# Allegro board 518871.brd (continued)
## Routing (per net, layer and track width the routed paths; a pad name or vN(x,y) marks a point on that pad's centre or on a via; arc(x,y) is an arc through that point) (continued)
GND_EARTH: length 19.9
  TOP w0.508: 7.77,114.68 2.26,114.68 J7.8 J7.6
VBAT: length 6.3
  TOP w0.508: 125.35,29.03 J4.1 ; J4.1 126.92,30.61 ; J4.1 125.35,32.18 ; J4.1 123.77,30.61
VBAT_SYS: length 43.3
  TOP w0.203: U18.15 v1(33.15,18.67)
  TOP w0.305: U79.10 v1(105.41,62.36)
  TOP w0.508: U606.5 118.13,105.01 v1(118.49,104.65) 118.93,105.08 U606.6
  TOP w0.635: TP1.1 99.95,27.23 ; TP1.1 99.26,26.54 ; TP1.1 100.64,26.54 ; TP1.1 99.95,25.86 ; 93.93,19.05 C23.1 ; C23.1 95.25,20.37 ; C23.1 95.25,17.73 ; C23.1 96.57,19.05 ; 53.92,19.05 C3.1 ; C3.1 56.57,19.05 ; C3.1 55.24,17.73
  LY5_PWR w0.635: C1.1 95.25,37.52 ; C1.1 93.93,36.2 ; C1.1 96.57,36.2 ; C1.1 95.25,34.87 ; 53.92,19.05 C3.1 ; C3.1 55.24,20.37 ; C3.1 56.57,19.05 ; C3.1 55.24,17.73 ; C23.1 96.57,19.05 ; C23.1 93.93,19.05 ; C23.1 95.25,20.37 ; C23.1 95.25,17.73 ; 55.24,34.87 C2.1 ; C2.1 55.24,37.52 ; C2.1 56.57,36.2 ; C2.1 53.92,36.2 ; TP1.1 100.64,26.54 ; TP1.1 99.95,25.86 ; TP1.1 99.26,26.54 ; TP1.1 99.95,27.23
  BOTTOM w0.305: RJ27.1 v1(105.41,62.36) C566.1
  vias: v1(16.89,15.11) v1(16.89,14.1) v1(18.16,15.11) v1(18.16,14.1) v1(19.43,15.11) v1(19.43,14.1) v1(24.64,19.05) v1(24.64,18.16) v1(25.4,19.05) v1(25.4,18.16) v1(26.16,19.05) v1(26.16,18.16) v1(33.02,17.65) v1(33.02,16.51) v1(37.08,16.26) v1(86.23,118.75) v1(86.23,117.47) v1(86.23,116.46) v1(90.17,117.86) v1(91.31,117.86) v1(92.46,117.86) v1(94.49,117.86) v1(95.63,117.86) v1(96.77,117.86) v1(100.08,24.26) v1(100.08,23.37) v1(100.08,22.48) v1(100.08,21.59) v1(102.49,26.04) v1(103.89,24.64) v1(103.89,23.24) v1(103.89,21.72)
VCC_LED_30V: length 18.9
  TOP w0.508: C628.1 v1(108.08,116.97) ; v1(110.36,116.97) 110.49,116.84 C635.2 111.38,114.3 112.14,113.54 112.14,112.52 112.56,112.11 U606.26
  LY4 w0.635: J24.3 125.81,77.19 ; J24.3 124.46,78.54 ; J24.3 123.11,77.19 ; J24.2 124.46,81.53 ; J24.2 124.46,78.84 ; J24.2 125.81,80.19 ; J24.2 123.11,80.19
  vias: v1(99.95,116.97) v1(101.09,116.97) v1(102.23,116.97) v1(103.38,116.97) v1(105.79,116.97) v1(106.93,116.97) v1(109.22,116.97)
VCC_LM5141: length 7.7
  TOP w0.305: U18.10 29.59,21.34 28.65,22.28 C45.1 26.47,22.28 25.48,21.29 D5.2
VDD__TX: length 1.8
  TOP w0.305: v1(86.82,88.34) 86.89,88.27 C429.1
  BOTTOM w0.305: v1(86.82,88.34) U77.31
VDD_CORE_AVS: length 114
  TOP w0.102: 49.33,85.62 49.72,85.62 ; 47.14,79.11 46.72,79.11 46.71,79.1 ; v3(47.9,85.62) 47.84,85.62 48.44,85.62 ; 50.63,85.62 51.02,85.62 ; 47.12,85.62 46.73,85.62
  TOP w0.203: U27.V10 52.13,84.64 U27.U9 ; U27.N11 U27.P10 ; U27.M17 U27.N18 ; 49.72,85.62 v3(49.85,85.62) ; U27.J16 47.25,79.11 47.14,79.11 ; U27.V12 50.51,85.62 50.63,85.62 ; 48.44,85.62 48.55,85.62 U27.V14 ; U27.N15 U27.P14 ; U27.J18 46.71,79.1 ; 47.12,85.62 47.25,85.62 U27.V16 ; U27.V18 46.61,85.62 46.73,85.62 ; U27.L12 U27.M11 ; v3(49.2,85.62) 49.33,85.62 ; v3(51.15,85.62) 51.02,85.62 51.02,85.62 ; 50.18,83.34 U27.R12 ; 48.02,85.62 v3(47.9,85.62) ; U27.K18 U27.L17 ; U27.N13 U27.P12 ; U27.R10 U27.T9
  TOP w0.254: U27.W12 v3(49.85,85.62) U27.V12 ; U27.T15 48.23,83.99 U27.R16 v3(47.25,83.67) ; U27.T15 v3(48.55,84.32) U27.U15 ; U27.T15 U27.R14 U27.T13 ; U27.T13 U27.R12 U27.T11 ; U27.T13 v3(49.85,84.32) U27.U13 ; U27.K18 v3(45.95,79.77) U27.J18 ; U27.V16 v3(47.9,85.62) U27.W16 ; U27.T11 v3(51.15,84.32) U27.U11 ; U27.T11 50.83,83.99 U27.R10 ; v3(50.5,83.02) 50.5,83.02 50.18,83.34 ; U27.V18 v3(46.6,84.97) 46.53,84.92 U27.U18 ; U27.P18 U27.R17 U27.P16 ; U27.W10 v3(51.15,85.62) U27.V10 ; U27.T9 v3(52.45,84.32) U27.U9 ; U27.V14 v3(49.2,85.62) U27.W14
  TOP w0.305: U27.P14 v3(49.2,83.02) U27.R14 ; U27.J16 47.9,79.68 U27.J15 ; U27.N15 v3(48.55,81.72) U27.M15 ; v3(47.9,83.02) U27.R16 ; U27.N13 v3(49.85,81.72) U27.M13 ; U27.M17 v3(47.25,81.07) U27.L17 ; v3(50.5,80.42) U27.K12 ; U27.N11 v3(51.15,81.72) U27.M11 ; v1(41.27,48.01) 41.66,48.39 U602.8 ; U27.P12 v3(50.5,83.02) ; U27.R10 v3(51.8,83.02) U27.P10 ; U27.P18 v3(45.95,82.37) U27.N18 ; U27.R17 v3(47.25,83.67) U27.T17
  LY5_PWR w0.102: v1(41.27,48.01) 41.34,48.01 43.56,50.23 43.56,50.85 44.81,52.1 44.81,52.6 44.07,53.34 44.07,60.07 48.39,64.39 50.8,64.39 50.95,64.24 51.66,64.24 52.45,65.02 59.82,65.02 61.34,66.55 61.34,67.44 61.21,67.56 61.21,70.38 61.57,70.74 61.57,73.56 58.04,77.09 58.04,78.74 56.64,80.14 52.7,80.14 52.58,80.26
  BOTTOM w0.254: v3(50.5,80.42) 50.68,80.65 50.9,80.87 50.93,80.87 C347.1 ; C321.1 v3(49.85,85.62) ; C332.1 v3(50.5,83.02) ; C341.1 v3(48.55,81.72)
  BOTTOM w0.381: C348.1 49.85,81.71 v3(49.85,81.72) ; v1(63.63,82.62) 63.63,82.42 64.01,82.03 C344.1 ; v1(63.16,87.58) C303.1 v1(65.71,87.58) ; v2(65.66,80.03) C373.1 v2(63.19,80.03) ; C347.1 51.16,81.72 v3(51.15,81.72)
  BOTTOM w0.406: C344.1 64.75,82.03 65.15,82.44 v1(65.15,82.62) ; v1(60.02,90.37) C551.1 v1(62.41,90.37) ; v1(62.61,83.93) C323.1 65.22,83.93 v1(65.28,83.99)
  vias: v1(46.86,50.8) v1(47.62,52.32) v1(48.51,52.32) v1(49.53,53.47) v1(49.53,52.58) v1(49.53,51.69) v1(49.53,50.8)
VDD_DDR_1V35: length 126.1
  TOP w0.254: U27.W20 v3(44.65,85.62) U27.V20 ; U27.T20 v3(45.3,84.32) U27.T19 ; v1(5.02,77.08) C98.1 v1(7.43,77.08) ; v1(7.24,84.33) C89.1 v1(4.83,84.33) ; U27.W17 v3(46.6,86.27) 46.28,85.95 U27.W18
  TOP w0.305: U29.R9 v2(9.51,74.51) ; U29.K8 v2(13.51,75.31) ; C80.2 12.13,100.52 v1(10.79,99.19) ; U29.K2 v2(13.51,80.9) ; U29.E9 v2(18.31,74.51) ; U23.R1 v2(9.51,95.93) ; U23.A8 v2(21.51,89.53) ; U23.K8 v2(13.51,89.53) ; v1(24.84,78) C96.1 v1(23.55,78.03) ; U29.H9 v2(15.91,74.51) ; U23.N1 v2(11.11,95.93) ; U29.A1 v2(21.51,81.7) ; U23.C1 v2(19.91,95.93) ; U29.N1 v2(11.11,81.7) ; U29.B2 v2(20.71,80.9) ; U29.N9 v2(11.11,74.51) ; U23.C9 v2(19.91,88.73) ; U29.G7 v2(16.71,76.11) ; U23.E9 v2(18.31,88.73) ; U23.D9 v2(19.11,88.73) ; U29.D2 v2(19.11,80.9) ; v1(5.51,91.74) C84.1 v1(6.93,91.74) ; U23.H2 v2(15.91,95.13) ; U23.N9 v2(11.11,88.73) ; U23.R9 v2(9.51,88.73) ; U29.H2 v2(15.91,80.9) ; v1(32.38,59.69) 36.58,59.69 37.59,58.68 U602.21 ; U29.F1 v2(17.51,81.7) ; U23.B2 v2(20.71,95.13) ; U29.R1 v2(9.51,81.7) ; U23.H9 v2(15.91,88.73) ; U29.D9 v2(19.11,74.51) ; U23.F1 v2(17.51,95.93) ; U29.C9 v2(19.91,74.51) ; U23.G7 v2(16.71,90.33) ; U29.C1 v2(19.91,81.7) ; U23.K2 v2(13.51,95.13) ; U23.A1 v2(21.51,95.93) ; U23.D2 v2(19.11,95.13) ; U29.A8 v2(21.51,75.31)
  LY5_PWR w0.102: 45.34,83.31 45.34,81.15 44.31,80.12 39.1,80.12 32.13,73.15 32.13,68.67 32.17,68.63 32.17,59.91 v1(32.38,59.69)
  BOTTOM w0.254: C300.1 v2(21.51,89.53) ; C279.1 v2(17.51,95.93) ; v2(39.45,91.24) 39.81,91.6 C293.1 39.81,91.9 v2(40.25,92.35) ; C278.1 v2(21.51,95.93) ; C383.1 v2(15.91,74.51) ; v3(44.65,85.62) 44.52,85.75 C315.1 ; v2(36.35,90.2) 36.58,90.2 C295.1 37.05,90.52 v2(37.47,90.94) ; C319.1 v3(46.6,86.27) ; C337.1 v2(17.51,81.7) ; v2(37.97,90.5) 38.31,90.85 C294.1 38.43,91.06 v2(38.84,91.47) ; v2(34.49,87.36) C311.1 v2(34.49,86) ; v2(32.72,85.98) C312.1 v2(32.72,87.33) ; v2(39.88,90.68) 40.01,90.56 C297.1 v2(40.77,90.04) ; 30,87.5 29.7,87.8 C307.1 ; C280.1 v2(11.11,95.93) ; C336.1 v2(21.51,81.7) ; C305.1 v2(15.91,88.73) ; C304.1 v2(19.91,88.73) ; C382.1 v2(19.91,74.51) ; C378.1 v2(21.51,75.31) ; C338.1 v2(11.11,81.7)
  BOTTOM w0.305: v1(17.42,99.19) C273.1 v1(17.37,97.38) ; v1(20.65,97.38) C272.1 v1(20.62,99.19) ; v1(23.05,75.69) C377.1 ; v1(15.82,85.65) C314.1 v1(15.8,87.07) ; v1(10.79,84.96) C328.1 v1(10.79,83.19) ; v1(17.65,84.96) C327.1 v1(17.14,83.19) ; v1(8.64,71.88) C386.2 v1(8.64,73.79) ; v1(10.79,99.19) C274.1 v1(10.79,97.41) ; v1(19.84,72.85) C391.1 v1(19.79,71.42) ; v1(15.62,71.47) C392.1 v1(15.56,73.03) ; C325.1 45.33,84.29 v3(45.3,84.32) ; v1(20.7,84.91) C326.1 v1(20.62,83.24) ; v1(19.84,85.65) C313.1 v1(19.81,87.07) ; C299.1 v1(23.05,89.92)
  BOTTOM w0.381: v2(26.75,80.14) C352.1 v2(26.75,81.46) ; v2(28.52,81.45) C351.1 v2(28.52,80.14) ; v2(30.38,81.42) C354.1 v2(30.38,80.12) ; v2(29.59,88.78) 29.46,88.65 29.46,87.95 C307.1 ; v2(30.63,87.5) 30,87.5
  BOTTOM w0.406: v2(39.25,94.12) C289.1 v2(41.71,94.12)
  vias: v1(4.7,63.5) v1(6.99,63.5) v1(8,63.5) v1(9.78,63.5) v1(12.32,56.52) v1(12.32,55.5) v1(12.32,54.48) v1(12.32,53.47) v1(12.45,58.04) v1(12.57,49.4) v1(12.7,63.63) v1(13.34,58.04) v1(14.1,63.63) v1(14.22,58.04) v1(15.37,63.63) v1(17.78,63.63) v1(19.18,63.63) v1(20.7,63.63) v1(29.72,53.21) v1(32.26,54.74) v1(32.26,53.09) v1(32.38,53.98)
VDD_DSP_AVS: length 77.8
  TOP w0.102: 52.45,78.47 v3(52.45,77.82) ; v3(50.5,77.82) 50.5,78.47 50.51,78.47 ; 49.97,78.48 49.97,78.47 50.39,78.47 ; 49.98,79.77 50.38,79.77 ; 51.68,78.47 51.28,78.47
  TOP w0.203: 51.28,78.47 51.15,78.47 ; 51.81,78.47 51.68,78.47 ; 50.38,79.77 50.5,79.77 ; 49.84,79.75 49.85,79.77 49.98,79.77 ; 50.51,78.47 50.39,78.47 ; 49.97,78.48 49.85,78.48
  TOP w0.305: U27.J9 v3(52.45,79.12) U27.H9 ; U602.1 v1(37.59,49.66) ; U27.H11 50.83,78.79 v3(51.15,79.12) U27.J11 50.5,79.77 ; U27.H11 50.51,78.47 ; U27.H11 51.15,78.47 ; U27.J13 49.53,79.44 v3(49.2,79.12) U27.H13 ; U27.J13 v3(49.85,79.12) 49.85,79.12 U27.H13 ; U27.J13 49.53,79.44 49.84,79.75 ; U27.H13 49.85,78.48 ; U27.H9 52.45,78.47 ; U27.H9 51.81,78.47
  LY5_PWR w0.102: 57.02,78.61 57.4,78.61 57.53,78.49 57.53,76.96 60.96,73.53 60.96,70.87 60.83,70.74 60.83,69.72 60.33,69.21 60.33,66.29 59.44,65.41 51.18,65.41 50.67,64.9 46.71,64.9 43.56,61.75 43.56,53.21 43.15,52.81 43.15,52.16 43.18,52.13 43.18,50.42 41.38,48.62 38.63,48.62 v1(37.59,49.66)
  BOTTOM w0.254: C362.1 v3(51.15,79.12) ; v2(59.8,70.93) C393.1 58.06,72.66 v2(58.05,72.66) ; v3(49.85,79.12) C361.1 ; v2(54.25,70.99) 54.27,70.98 C403.1 v2(54.27,68.46)
  BOTTOM w0.305: C357.1 52.92,79.57 52.65,79.31 v3(52.45,79.12) ; C370.1 v3(52.45,77.82)
  BOTTOM w0.381: v2(38.45,72.29) 38.45,72.29 39.4,73.22 40.28,74.08 v2(40.31,74.08)
  BOTTOM w0.406: v2(52.13,71) C402.1 v2(52.13,68.55) ; v2(48.59,71) C401.1 v2(48.59,68.56)
  vias: v1(29.72,51.44) v1(32.26,50.04) v1(32.38,51.69) v1(32.38,50.8) v1(33.64,66.77) v1(34.23,66.09) v1(34.84,66.72) v1(35.32,66.11) v1(35.98,66.77) v1(36.51,66.11) v1(37.2,66.72) v1(37.68,66.11) v1(38.24,66.75) v1(38.87,66.11) v1(39.46,66.72)
VDD_VID: length 14.3
  TOP w0.305: v1(86.87,87) C568.1 ; L16.1 v1(98.17,80.14) ; v1(87.5,80.64) 87.63,80.77 C410.1 ; C129.1 v1(98.17,78.61) ; C409.1 v1(96.52,80.61)
  TOP w0.508: v1(86.87,87) 85.85,85.98 85.85,81.79 87,80.64 v1(87.5,80.64)
  BOTTOM w0.305: v1(96.52,80.61) U77.64 ; U77.28 87.02,86.84 v1(86.87,87) ; 88.33,80.64 v1(87.5,80.64)
VDDA_LM5141: length 12.1
  TOP w0.203: v1(30.86,27.3) R35.2 R34.2 ; U18.2 34.15,24.37 34.42,24.64 v1(34.42,24.7) C53.1
  BOTTOM w0.305: v1(30.86,27.3) 31.5,27.94 33.27,27.94 34.04,27.18 34.04,25.08 v1(34.42,24.7) 34.99,25.27 R221.2
VDDI_MMC2: length 2.7
  TOP w0.305: U31.E4 v1(78.77,67.75)
  BOTTOM w0.305: C433.1 79.38,68.35 v1(78.77,67.75) 78.7,67.82 C436.1
VDDR_VREFSTL: length 129.5
  TOP w0.254: C164.2 v2(10.16,45.47) ; U29.M8 v2(11.91,75.31) ; U27.Y20 v3(44.65,86.92) ; C91.1 v1(16.05,84.33)
  TOP w0.305: U35.6 10.21,45.52 v2(10.16,45.47) ; U23.H1 v2(15.91,95.93) ; U23.M8 v2(11.91,89.53) ; C91.1 15.3,85.14 14.8,85.64 v1(12.58,85.64) ; U29.H1 v2(15.91,81.7)
  TOP w0.381: v2(15.91,95.93) 15.91,98.01 C82.1 C80.1
  TOP w0.508: v1(3.68,62.48) 3.68,69.98 4.83,71.12 9.4,71.12 v1(10.16,71.88) 10.79,71.25 13.59,71.25 14.35,72.01 v2(14.35,74.3)
  LY3 w0.381: v2(11.91,89.53) 11.98,89.53 12.58,88.93 12.58,85.64 v1(12.58,85.64)
  LY4 w0.381: v2(15.91,95.93) 16.43,96.45 22.17,96.45 22.71,95.91 35.53,95.91 37.08,94.36 37.21,94.36 40.64,90.93 40.64,90.65 40.25,90.26 40.25,87.89 41.53,86.61 43.18,86.61 43.43,86.36 44.32,86.36 44.65,86.69 v3(44.65,86.92)
  BOTTOM w0.305: C386.1 v1(10.16,71.88)
  BOTTOM w0.381: v2(11.91,75.31) 11.94,75.31 13.29,73.96 14.02,73.96 v2(14.35,74.3) 15.22,75.17 15.22,81.02 v2(15.91,81.7) 15.91,82.84 16.1,83.03 16.1,84.28 v1(16.05,84.33) 15.1,85.28 15.1,88.38 15.39,88.67 15.39,90.54 15.7,90.85 18.95,90.85 19.33,91.23 19.33,93.4 18.92,93.81 15.7,93.81 15.39,94.11 15.39,95.34 15.72,95.67 15.72,95.74 v2(15.91,95.93)
  BOTTOM w0.508: v2(10.16,45.47) 10.16,46.99 8.64,48.51 8.64,57.53 v1(3.68,62.48)
VDDS_1V8: length 87.9
  TOP w0.254: U27.W7 v3(53.1,85.62) ; U27.Y18 v3(45.95,86.27) U27.Y19 v3(45.95,86.92) ; v3(45.95,87.57) U27.AA19 ; v3(44.65,83.02) U27.P20 ; U27.G11 50.83,78.14 v3(51.15,77.82) ; U27.H20 v3(44.65,78.47) ; U27.P7 v3(53.1,83.02) U27.R7 ; v3(53.75,79.77) U27.J7 ; U27.H7 53.58,78.65 53.58,78.29 U27.G7 v3(53.75,77.82) U27.F7
  TOP w0.305: U31.P3 v1(77.77,57.74) ; L17.2 v1(87.88,93.73) ; U31.H8 v1(83.77,64.75) ; U31.P8 v1(83.77,57.74) ; U31.L7 v1(82.77,60.74) ; U26.2 52.68,121.92 51.43,121.92 v1(51.31,122.05) ; U27.K8 v3(52.46,79.77) 52.78,79.44 U27.J8 ; U31.L4 v1(78.77,60.74) ; L16.2 v1(101.47,80.14) ; U31.L9 v1(84.78,60.74) ; U31.L2 v1(76.77,60.74) ; U31.H3 v1(77.77,64.75)
  TOP w0.381: v2(36.09,75.41) C108.1 38.2,75.41 v2(38.35,75.56)
  LY4 w0.203: v3(51.15,77.82) 50.75,78.22 49.16,78.22 48.9,78.49 48.5,78.49
  LY4 w0.508: v1(71.27,114.55) 68.58,114.55 65.79,117.35 61.09,117.35 54.48,123.95 53.21,123.95 v1(51.31,122.05)
  BOTTOM w0.254: C318.1 v3(53.1,85.62) ; C298.1 45.95,89.15 v3(45.95,87.57) v3(45.95,86.92) 45.96,86.84 v3(45.95,86.27)
  BOTTOM w0.305: RJ22.3 v1(91.95,76.33) ; v1(95.24,74.81) 95.5,75.07 RJ21.3 ; RJ25.3 RJ23.3 RJ18.3 ; RJ25.3 v1(81.15,83.82) ; RJ25.3 RJ24.3 RJ30.1 ; R271.1 75.95,59.92 v1(76.77,60.74) ; RJ28.1 v1(84.84,87.76) ; RJ29.1 v1(101.47,87.12) ; R296.2 79.49,61.47 v1(78.77,60.74) ; RJ17.1 v1(101.47,84.2) ; v1(72.01,114.3) 71.77,114.06 P9.40 ; v3(53.1,83.02) 53.16,83.07 C342.1 ; R269.1 v1(77.72,62.74) R273.1 ; R300.1 82.25,55.88 82.55,56.18 v1(82.55,56.52) ; P9.38 v1(71.27,114.55) ; v1(82.77,60.74) 82.93,60.59 R289.1 ; C283.1 53.79,79.73 v3(53.75,79.77) ; v1(51.31,122.05) 51.44,122.17 R245.1 R246.1 ; v1(83.77,57.74) 83.57,57.53 C427.1 ; R295.1 v1(81.79,58.8) ; RJ20.3 v1(97.66,77.6) ; R241.2 v1(74.68,81.28) ; v1(83.77,64.75) 83.57,64.54 C411.1 ; R254.1 v1(79.76,88.9) ; v1(84.78,60.74) 84.81,60.71 R268.1 R270.1 ; R250.1 v1(78.49,88.9) ; RJ16.1 v1(100.71,81.28) ; R247.2 v1(77.22,81.28) ; R243.2 v1(75.95,81.28) ; v1(81.79,62.74) 81.92,62.61 R272.1 ; R258.1 v1(81.03,88.9) ; RJ19.3 v1(94.11,77.6)
  vias: v1(67.69,95) v1(68.58,95) v1(68.58,94.11) v1(68.58,93.22)
CAN_POWER_ON_HV: length 94.4
  TOP w0.127: SW2.4 27.81,37.08 v1(33.66,42.93)
  LY4 w0.133: v1(33.66,42.93) 95.89,42.93 109.22,56.26 v1(109.22,57.02)
  BOTTOM w0.127: R436.1 v1(109.22,57.02)
CAN_WAKE: length 17.8
  BOTTOM w0.127: J17.10 115.52,59.89 114.05,58.42 110.62,58.42 v1(106.68,62.36) ; RJ27.2 105.16,61.34 106.17,62.36 v1(106.68,62.36) ; v1(106.68,62.36) R435.2
CANH_1: length 20.2
  TOP w0.127: U79.13 101.6,65.15 103.12,66.67 109.73,66.67 112.5,63.91 J17.4
  BOTTOM w0.127: J17.4 116.2,64.01 R388.1
CANL_1: length 19.3
  TOP w0.127: J17.3 116.23,61.98 113.28,61.98 109.22,66.04 103.76,66.04 102.87,65.15 U79.12
  BOTTOM w0.127: R152.2 116.13,61.72 J17.3
CON_MMC1_CLK: length 8.3
  BOTTOM w0.127: R406.2 109.47,92.33 110.36,92.33 110.46,92.43 111.73,92.43 112.15,92.84 U67.3 112.58,92.84 114.81,92.84 115.28,92.36 P10.5
CON_MMC1_CMD: length 8
  BOTTOM w0.127: P10.3 112.09,94.56 111.37,93.85 U67.5 109.1,93.85 R405.2
CON_MMC1_DAT0: length 8.6
  BOTTOM w0.127: R407.2 109.1,91.31 U66.5 111.33,91.31 111.84,91.82 113.41,91.82 115.07,90.16 P10.7
CON_MMC1_DAT1: length 8.5
  BOTTOM w0.127: R408.2 109.6,90.04 109.82,89.83 111.8,89.83 112.28,90.3 U66.3 114.17,90.3 115.4,89.07 P10.8
CON_MMC1_DAT2: length 8
  BOTTOM w0.127: R403.2 109.1,96.39 U68.5 111.37,96.39 111.89,96.9 114.05,96.9 114.18,96.76 P10.1
CON_MMC1_DAT3: length 8.2
  BOTTOM w0.127: R404.2 109.47,94.87 110.74,94.87 110.84,94.97 111.86,94.97 112.28,95.38 U68.3 113.55,95.38 113.83,95.66 P10.2
CONN_USB_D+: length 9.7
  TOP w0.13: v2(9.53,119.05) 9.32,119.25 8,119.25 J7.3
  BOTTOM w0.122: v2(9.53,119.05) 9.83,119.35 16.6,119.35 16.71,119.24 U52.14
CONN_USB_D-: length 9.7
  TOP w0.13: J7.2 8.04,119.76 9.37,119.76 v2(9.53,119.91)
  BOTTOM w0.122: v2(9.53,119.91) 9.8,119.63 16.61,119.63 16.71,119.74 U52.15
EMAC[1]_RXC: length 72.3
  TOP w0.127: U40.27 v1(92.23,55.6) ; U27.E11 v3(50.5,76.52)
  LY3 w0.133: v1(92.23,55.6) 91.82,56.01 91.59,56.01 91.43,55.85 91.43,55.66 91.27,55.5 91.05,55.5 90.9,55.66 90.9,56.23 90.74,56.39 90.52,56.39 90.36,56.23 90.36,55.66 90.21,55.5 89.99,55.5 89.83,55.66 89.83,56.22 89.66,56.39 89.03,56.39 87.25,54.61 67.69,54.61 67.18,54.1 64.23,54.1 64.08,54.26 64.08,54.45 63.92,54.61 63.7,54.61 63.55,54.45 63.55,54.26 63.39,54.1 63.17,54.1 63.01,54.26 63.01,54.45 62.86,54.61 62.63,54.61 62.48,54.45 62.48,54.26 62.32,54.1 62.1,54.1 61.95,54.26 61.95,54.45 61.79,54.61 61.57,54.61 61.41,54.45 61.41,54.26 61.26,54.1 61.03,54.1 60.88,54.26 60.88,54.45 60.72,54.61 60.5,54.61 60.34,54.45 60.34,54.26 60.19,54.1 59.97,54.1 59.81,54.26 59.81,54.45 59.66,54.61 59.43,54.61 59.28,54.45 59.28,54.26 59.12,54.1 58.9,54.1 58.74,54.26 58.74,54.45 58.59,54.61 58.37,54.61 58.21,54.45 58.21,54.26 58.06,54.1 57.83,54.1 57.68,54.26 57.68,54.45 57.52,54.61 57.3,54.61 57.14,54.45 57.14,54.26 56.99,54.1 56.77,54.1 56.61,54.26 56.61,54.45 56.45,54.61 55.89,54.61 v1(55.5,54.23)
  BOTTOM w0.127: v3(50.5,76.52) 51.12,75.9 51.12,73.98 50.67,73.53 50.67,64.39 51.31,63.75 53.34,63.75 54.23,62.87 54.23,62.23 54.74,61.72 54.74,58.04 55.5,57.28 v1(55.5,54.23)
EMAC[1]_RXCTL: length 73.9
  TOP w0.127: U27.F11 v3(50.5,77.17) ; U40.15 v1(98.54,53.2)
  LY3 w0.133: v1(53.47,54.23) 54.48,54.23 54.99,53.72 67.44,53.72 67.99,54.27 87.67,54.27 88.53,55.13 91.69,55.13 91.95,54.86 96.88,54.86 v1(98.54,53.2)
  BOTTOM w0.102: v3(50.5,77.17) 49.99,77.17 49.02,76.2 49.02,74.33 49.19,74.17 49.19,73.65 49.15,73.61 49.15,73.51
  BOTTOM w0.127: v1(53.47,54.23) 53,54.23 51.18,56.05 51.18,58.42 49.15,60.45 49.15,73.51
EMAC[1]_RXD0: length 71.7
  TOP w0.127: U27.D13 v3(49.85,75.87) ; U40.26 v1(93.37,56.36)
  LY3 w0.133: v1(93.37,56.36) 92.86,56.36 92.08,57.15 88.01,57.15 87.5,57.66 87.29,57.66 87.11,57.48 87.11,57.29 87.73,56.67 87.73,56.48 86.61,55.37 67.06,55.37 66.55,54.86 65.79,54.86 65.28,55.37 55.75,55.37 54.48,56.64 v1(51.98,56.64)
  BOTTOM w0.127: v3(49.85,75.87) 49.48,75.49 49.48,74.98 49.66,74.8 49.66,62.87 50.6,61.92 50.6,61.71 49.92,61.04 49.92,60.82 50.07,60.68 50.28,60.68 50.96,61.35 51.17,61.35 51.32,61.21 51.32,61 50.64,60.32 50.64,60.11 50.79,59.96 51,59.96 51.68,60.64 51.89,60.64 52.58,59.94 52.58,57.24 v1(51.98,56.64)
EMAC[1]_RXD1: length 71.4
  TOP w0.127: U40.25 93.87,56.75 v1(93.34,57.28) ; U27.C13 v3(49.85,75.22)
  LY3 w0.133: v1(93.34,57.28) 93.34,59.18 92.96,59.56 92.73,59.56 92.57,59.41 92.57,58.2 92.42,58.04 92.2,58.04 92.04,58.2 92.04,59.41 91.88,59.56 91.66,59.56 91.51,59.41 91.51,58.2 91.35,58.04 91.13,58.04 90.97,58.2 90.97,59.41 90.69,59.69 88.01,59.69 85.26,56.94 82.17,56.94 81.37,56.13 61.34,56.13 60.87,56.6 57.06,56.6 56.13,57.53 v1(53.47,57.53)
  BOTTOM w0.127: v1(53.47,57.53) 53.47,60.58 51.44,62.61 50.67,62.61 49.91,63.37 49.91,73.61 49.89,73.64 49.89,74.9 49.85,74.93 v3(49.85,75.22)
EMAC[1]_RXD2: length 71.6
  TOP w0.127: U40.24 v1(94.37,56.38) ; U27.E13 v3(49.85,76.52)
  LY3 w0.133: v1(53.47,56.01) 53.47,55 53.6,54.86 53.89,54.86 54.05,55.02 54.05,55.85 54.2,56.01 54.42,56.01 54.58,55.85 54.58,55.15 54.74,54.99 64.3,54.99 64.85,54.44 66.76,54.44 67.31,54.99 86.87,54.99 88.65,56.77 91.82,56.77 92.65,55.94 92.65,55.43 92.84,55.24 94.11,55.24 94.37,55.51 v1(94.37,56.38)
  BOTTOM w0.127: v1(53.47,56.01) 51.82,56.01 51.56,56.26 51.56,58.67 49.4,60.83 49.4,74.55 49.25,74.7 49.25,75.91 v3(49.85,76.52)
EMAC[1]_RXD3: length 76
  TOP w0.102: 49.85,73.51 49.85,74.57 U27.B13
  TOP w0.127: v1(56.01,56.11) 56.01,57.78 55.59,58.2 55.59,63.28 52.45,66.42 52.45,66.65 51.6,67.5 50.61,67.5 49.78,68.33 49.78,71.71 49.85,71.78 49.85,73.51 ; v1(94.36,57.28) 94.87,56.77 U40.23
  LY3 w0.133: v1(94.36,57.28) 93.94,56.85 93.01,56.85 92.33,57.53 90.54,57.53 90.39,57.69 90.39,59.15 90.23,59.31 90.01,59.31 89.85,59.15 89.85,57.69 89.7,57.53 89.48,57.53 89.32,57.69 89.32,59.15 89.16,59.31 88.94,59.31 88.79,59.15 88.79,57.69 88.63,57.53 88.39,57.53 88.24,57.69 88.24,58.64 88.08,58.8 87.76,58.8 86.32,57.36 86.32,57.14 86.92,56.54 86.92,56.32 86.77,56.16 86.55,56.16 85.94,56.77 85.72,56.77 85.32,56.36 85.3,56.36 85.3,55.91 85.15,55.75 84.93,55.75 84.77,55.91 84.77,56.36 84.61,56.52 84.39,56.52 84.24,56.36 84.24,55.91 84.08,55.75 83.86,55.75 83.7,55.91 83.7,56.36 83.55,56.52 83.31,56.52 82.55,55.75 60.06,55.75 59.99,55.69 56.43,55.69 v1(56.01,56.11)
EMAC[1]_TXC: length 61.7
  TOP w0.127: R101.1 52.4,69.51 52.71,69.22 53.47,69.22 53.87,68.81 53.87,68.19 57.66,64.41 57.66,57.02 58.17,56.52 58.17,55.37 59.05,54.48 v1(59.05,53.09) ; U40.28 v1(91.19,54.7)
  LY3 w0.133: v1(91.19,54.7) 88.74,54.7 87.88,53.85 79.88,53.85 78.61,52.58 72.01,52.58 71.85,52.73 71.85,53.69 71.69,53.85 71.47,53.85 71.32,53.69 71.32,52.73 71.16,52.58 68.26,52.58 68.11,52.73 68.11,53.18 67.95,53.34 67.73,53.34 67.57,53.18 67.57,52.73 67.42,52.58 67.19,52.58 67.04,52.73 67.04,53.18 66.88,53.34 66.66,53.34 66.5,53.18 66.5,52.73 66.35,52.58 66.13,52.58 65.97,52.73 65.97,53.18 65.82,53.34 65.59,53.34 65.44,53.18 65.44,52.73 65.28,52.58 64.32,52.58 64.17,52.73 64.17,53.18 64.01,53.34 63.79,53.34 63.63,53.18 63.63,52.73 63.48,52.58 59.56,52.58 v1(59.05,53.09)
EMAC[1]_TXCTL: length 64.2
  TOP w0.127: U40.29 v1(90.42,54.2) ; U27.D11 v3(50.5,75.87)
  LY3 w0.133: v1(90.42,54.2) 88.75,54.2 87.88,53.34 80.01,53.34 78.74,52.07 58.8,52.07 57.57,53.3 v1(55.63,53.3)
  BOTTOM w0.127: v1(55.63,53.3) 54.36,54.57 54.36,61.51 53.26,62.61 52.45,62.61 51.69,63.37 50.93,63.37 50.42,63.88 50.42,73.91 50.89,74.39 50.89,75.48 v3(50.5,75.87)
EMAC[1]_TXD0: length 67.2
  TOP w0.127: U40.33 91.45,52.2 91.32,52.07 v1(90.68,52.07) ; v1(57.78,50.29) 57.02,51.05 57.02,54.1 55.5,55.63 55.5,57.66 55.24,57.91 55.24,63.12 51.94,66.42 51.18,66.42 49.53,68.07 U27.A13
  LY3 w0.133: v1(57.78,50.29) 58.8,49.28 62.1,49.28 63.16,50.33 63.4,50.33 63.55,50.18 63.55,49.43 63.71,49.28 63.93,49.28 64.08,49.43 64.08,50.18 64.24,50.33 64.46,50.33 64.62,50.18 64.62,49.43 64.77,49.28 65,49.28 65.15,49.43 65.15,50.04 65.45,50.33 77.05,50.33 77.22,50.16 87.25,50.16 89.16,52.07 v1(90.68,52.07)
EMAC[1]_TXD1: length 66.3
  TOP w0.127: U40.32 91.67,52.7 91.66,52.69 91.43,52.69 91.42,52.7 v1(91.19,52.7) ; v1(57.91,51.18) 57.4,51.69 57.4,54.74 56.52,55.63 56.52,62.99 51.76,67.75 50.74,67.75 50.04,68.45 50.04,71.61 50.18,71.75 U27.A12
  LY3 w0.133: v1(91.19,52.7) 89.15,52.7 87.12,50.67 62.02,50.67 61.86,50.52 61.86,49.94 61.7,49.78 61.48,49.78 61.33,49.94 61.33,50.52 61.17,50.67 60.95,50.67 60.79,50.52 60.79,49.94 60.64,49.78 60.42,49.78 60.26,49.94 60.26,50.52 60.1,50.67 59.88,50.67 59.73,50.52 59.73,49.94 59.57,49.78 59.35,49.78 59.19,49.94 59.19,50.52 59.04,50.67 58.42,50.67 v1(57.91,51.18)
EMAC[1]_TXD2: length 66.3
  TOP w0.102: U27.B12 50.5,74.57 50.5,73.51
  TOP w0.127: 50.5,73.51 50.5,71.71 50.29,71.5 50.29,68.71 51,68 52.01,68 56.9,63.12 56.9,55.88 58.55,54.23 58.55,52.45 59.31,51.69 v1(59.31,51.18) ; v1(90.42,53.2) U40.31
  LY3 w0.133: v1(59.31,51.18) 79.12,51.18 79.63,51.69 80.37,51.69 80.53,51.85 80.53,52.17 80.68,52.32 80.9,52.32 81.06,52.17 81.06,51.85 81.22,51.69 81.44,51.69 81.59,51.85 81.59,52.17 81.75,52.32 81.97,52.32 82.13,52.17 82.13,51.85 82.28,51.69 83.24,51.69 83.4,51.85 83.4,52.17 83.56,52.32 83.78,52.32 83.93,52.17 83.93,51.85 84.09,51.69 84.31,51.69 84.47,51.85 84.47,52.17 84.62,52.32 84.84,52.32 85,52.17 85,51.85 85.16,51.69 85.38,51.69 85.53,51.85 85.53,52.17 85.69,52.32 85.91,52.32 86.07,52.17 86.07,51.85 86.22,51.69 87.5,51.69 89.02,53.2 v1(90.42,53.2)
EMAC[1]_TXD3: length 63.7
  TOP w0.127: U27.C11 v3(50.5,75.22) ; U40.30 v1(91.19,53.7)
  LY3 w0.133: v1(54.9,52.87) 55.2,52.58 57.66,52.58 58.55,51.69 78.99,51.69 80.14,52.83 88.01,52.83 88.88,53.7 v1(91.19,53.7)
  BOTTOM w0.127: v1(54.9,52.87) 54.9,53.43 53.98,54.36 53.98,60.58 51.56,62.99 50.8,62.99 50.16,63.63 50.16,74.17 50.5,74.51 v3(50.5,75.22)
EMU_RSTN: length 69.8
  TOP w0.127: J14.6 v1(77.75,44.09)
  LY3 w0.133: v1(77.75,44.09) 74.47,47.37 64.01,47.37 63.5,47.88 57.66,47.88 53.21,52.32 51.82,52.32 50.42,53.72 50.42,58.15 46.84,61.72 44.07,61.72 43.68,62.11 33.14,62.11 30.61,64.64 v1(30.61,72.14)
  BOTTOM w0.127: v1(77.75,44.09) 77.85,44.2 R329.2 ; v1(30.61,72.14) 30.61,73.28 R263.2
EN_SDIO_3V3: length 18.2
  TOP w0.102: U27.Y1 58.09,86.59
  TOP w0.127: U604.1 70.95,94.02 70.87,94.11 R601.2 70.23,93.09 66.29,89.15 65.53,89.15 63.41,87.03 58.84,87.03 58.4,86.59 58.09,86.59
EN_STAGE1: length 22.6
  TOP w0.127: v1(31.88,36.2) SW2.1 32.89,37.08 33.02,37.21 33.02,38.1 32.77,38.35 SW2.2
  TOP w0.305: U18.23 35.73,22.34 v1(36.7,23.31) 37.34,23.94 C48.2
  LY4 w0.133: v1(31.88,36.2) 31.88,32 36.7,27.18 v1(36.7,23.31)
  BOTTOM w0.305: R401.1 36.7,23.5 v1(36.7,23.31)
ENET_EN: length 74.8
  TOP w0.102: U27.A15 48.23,74.07 48.51,73.79 48.51,73.51
  TOP w0.127: v1(95.76,49.02) 95.87,49.13 U40.7 ; v1(54.74,48.64) 54.74,51.44 54.1,52.07 54.1,56.39 53.98,56.52 53.98,62.74 51.56,65.15 50.29,65.15 47.28,68.16 47.28,71.16 47.51,71.39 47.61,71.39 48.51,72.29 48.51,73.51
  LY4 w0.133: v1(54.74,48.64) 64.14,48.64 65.42,47.36 74.16,47.36 74.68,47.88 78.23,47.88 79.5,49.15 87.76,49.15 88.14,48.77 89.66,48.77 90.42,49.52 92.84,49.52 93.34,49.02 v1(95.76,49.02)
  BOTTOM w0.127: R358.1 95.76,49.53 v1(95.76,49.02)
ENET_INH: length 76.6
  TOP w0.102: 46.84,73.51 46.84,73.76 46.93,73.85 U27.A17
  TOP w0.127: v1(98.55,49.78) 98.55,50.42 98.27,50.7 U40.10 ; v1(53.47,49.78) 53.47,51.18 52.58,52.07 52.58,59.69 49.15,63.12 49.15,64.52 46.23,67.44 46.23,71.75 46.84,72.36 46.84,73.51
  LY4 w0.133: v1(53.47,49.78) 65.66,49.78 67.31,48.13 72.64,48.13 73.53,49.02 77.22,49.02 78.11,49.91 93.22,49.91 93.34,49.78 v1(98.55,49.78)
  BOTTOM w0.127: v1(98.55,49.78) R365.1
ENET_INTSN: length 67.6
  TOP w0.102: 47.89,73.51 47.89,73.64 47.58,73.95 U27.A16
  TOP w0.127: 47.89,73.51 47.89,72.66 46.74,71.5 46.74,67.82 49.91,64.64 49.91,64.39 52.96,61.34 52.96,52.58 54.1,51.44 v1(54.1,49.28)
  LY4 w0.133: v1(89.03,49.28) 88.78,49.52 79.37,49.52 78.06,48.22 73.62,48.22 73.15,47.75 67.06,47.75 65.53,49.28 v1(54.1,49.28)
  BOTTOM w0.127: R346.1 R342.1 v1(89.03,49.28)
ENET_WAKE: length 75.4
  TOP w0.102: 49.02,73.51 49.02,74.1 U27.A14
  TOP w0.127: 49.02,73.51 49.02,67.82 49.15,67.69 49.15,67.06 50.67,65.53 51.82,65.53 54.36,62.99 54.36,56.77 54.48,56.64 54.48,52.32 55.37,51.44 v1(55.37,47.75) ; v1(96.65,48.51) 96.37,48.79 U40.8
  LY4 w0.133: v1(96.65,48.51) 95.76,47.62 91.31,47.62 90.81,48.13 80.77,48.13 79.38,46.74 65.02,46.74 64.01,47.75 v1(55.37,47.75)
  BOTTOM w0.127: v1(96.65,48.51) R360.1
FB_5141: length 3.7
  TOP w0.203: U18.19 35.53,20.35 36.83,19.05 R26.2 R24.1
GP6_10/EHRPWM2A: length 94
  TOP w0.102: v1(55.12,90.55) 55.03,90.47 55.03,86.9 U27.Y5
  TOP w0.127: v1(112.01,100.46) 113.16,101.6 121.41,101.6 124.08,104.27 124.08,108.97 124.46,109.35 124.46,113.16 123.38,114.23 U606.17
  LY4 w0.102: v1(55.12,90.55) 55.12,90.58
  LY4 w0.133: 55.12,90.58 55.85,91.31 65.79,91.31 66.67,90.42 72.77,90.42 74.68,92.33 101.09,92.33 109.64,100.88 111.59,100.88 v1(112.01,100.46)
  BOTTOM w0.127: R610.2 v1(112.01,100.46)
GP6_11/EHRPWM2B: length 95
  TOP w0.102: U27.Y6 54.38,86.9 54.38,90.58
  TOP w0.127: U606.18 v1(119.73,115.32) ; Q602.5 v1(108.2,102.23) ; v1(54.38,90.93) 54.38,90.58
  LY4 w0.133: v1(54.38,90.93) 55.15,91.69 64.77,91.69 65.02,91.95 68.96,91.95 70.74,93.73 73.28,93.73 73.91,93.09 100.84,93.09 108.2,100.46 v1(108.2,102.23) 109.98,104.01 118.75,104.01 121.67,106.93 121.67,108.97 123.83,111.12 123.83,113.41 121.92,115.32 v1(119.73,115.32)
  BOTTOM w0.127: v1(108.2,102.23) 107.95,101.98 R611.2
GPIO1_22/EHRPWM3A: length 85
  TOP w0.102: U27.Y3 56.33,86.89 56.33,90.31 v1(56.13,90.51)
  TOP w0.127: v1(110.87,100.46) 112.52,102.11 121.16,102.11 123.7,104.65 123.7,108.71 123.5,108.91 U606.11
  LY4 w0.102: 56.24,90.58 56.18,90.51 v1(56.13,90.51)
  LY4 w0.133: v1(110.87,100.46) 110.11,99.69 109.22,99.69 101.47,91.95 74.93,91.95 73.03,90.04 66.42,90.04 65.53,90.93 56.6,90.93 56.24,90.58
  BOTTOM w0.127: R609.2 v1(110.87,100.46)
GPIO7_2: length 97.9
  TOP w0.102: 58.09,86.24 56.98,86.24 U27.W2
  TOP w0.127: v1(72.39,90.89) 72.39,87.88 71.37,86.87 70.36,86.87 69.98,86.49 61.34,86.49 61.05,86.19 60.28,86.19 60.23,86.24 58.09,86.24 ; v1(113.16,100.46) 113.79,101.09 121.67,101.09 124.59,104.01 124.59,108.84 124.97,109.22 124.97,113.54 122.56,115.95 119.27,115.95 118.93,115.61 U606.19
  LY4 w0.133: v1(113.16,100.46) 111.76,101.86 109.1,101.86 108.71,101.47 108.71,100.46 100.97,92.71 74.21,92.71 v1(72.39,90.89)
  BOTTOM w0.127: R608.2 v1(113.16,100.46)
H_CSI2_DX0: length 44.5
  TOP w0.102: U27.AC1 57.49,88.54 57.51,88.57
  TOP w0.112: v1(59.05,116.84) 59.46,116.43 59.46,115.08 59.35,114.97 58.89,114.97 58.78,114.85 58.78,114.66 58.91,114.52 59.35,114.52 60.3,113.57 60.3,110.13 60.19,110.02 57.62,110.02 57.28,109.68 57.28,109.2 57.62,108.86 60.22,108.86 60.35,108.73 60.35,108.55 60.22,108.42 57.62,108.42 57.28,108.08 57.28,107.6 57.62,107.26 60.22,107.26 60.35,107.13 60.35,93.87 59.25,92.78 59.25,89.6 58.24,88.58 57.6,88.58 57.59,88.57 57.51,88.57
  BOTTOM w0.112: v1(59.05,116.84) 59.28,117.06 P9.5
H_CSI2_DX1: length 44.5
  TOP w0.112: U27.AD1 57.57,89.19 58.04,89.66 58.04,93.6 58.93,94.49 58.93,103.92 55.14,107.7 55.14,109.88 57.28,112.01 58.56,112.01 58.67,112.13 58.67,113.22 58.56,113.34 56.71,113.34 56.13,113.91 56.13,115.44 56.45,115.76 57.34,115.76 57.45,115.88 57.45,117.09 58.27,117.91 60.43,117.91 60.85,118.32 60.85,118.58 60.74,118.69 60.18,118.69 60.07,118.8 60.07,119.03 60.18,119.14 60.74,119.14 60.91,119.31 60.91,119.81 v1(60.64,120.08)
  BOTTOM w0.112: v1(60.64,120.08) 60.78,119.95 P9.9
H_CSI2_DX2: length 44
  TOP w0.102: U27.AE2 56.68,89.95 56.68,89.96 56.68,90.13
  TOP w0.112: 56.68,90.13 56.68,103.72 53.37,107.04 53.37,115.21 56.51,118.35 56.8,118.35 56.85,118.41 56.97,118.41 57.02,118.47 v1(57.02,118.88)
  BOTTOM w0.112: v1(57.02,118.88) 57.02,118.58 56.8,118.35 56.4,118.35 56.26,118.49 56.26,119.13 57.74,120.61 59.35,120.61 59.58,120.38 59.58,120 59.69,119.89 59.89,119.89 60.02,120.03 60.02,120.47 60.15,120.61 62.28,120.61 62.42,120.47 62.42,119.82 62.27,119.68 P9.13
H_CSI2_DY0: length 44.5
  TOP w0.102: U27.AB2 57,88.21 57.51,88.21
  TOP w0.112: v1(59.82,116.84) 59.82,114.55 60.66,113.72 60.66,109.99 60.34,109.67 57.76,109.67 57.63,109.53 57.63,109.35 57.76,109.22 60.37,109.22 60.71,108.88 60.71,108.4 60.37,108.06 57.76,108.06 57.63,107.93 57.63,107.74 57.76,107.61 60.37,107.61 60.71,107.27 60.71,93.73 59.61,92.63 59.61,89.45 58.38,88.23 57.75,88.23 57.73,88.21 57.51,88.21
  BOTTOM w0.112: v1(59.82,116.84) 59.78,116.88 P9.7
H_CSI2_DY1: length 44.5
  TOP w0.102: 57.79,88.9 57.78,88.89 57.03,88.89 U27.AC2
  TOP w0.112: v1(61.4,120.08) 61.26,119.94 61.26,119.16 61.2,119.1 61.2,118.18 60.58,117.55 58.42,117.55 57.81,116.94 57.81,115.73 57.49,115.41 56.6,115.41 56.49,115.3 56.49,114.06 56.86,113.69 58.71,113.69 59.03,113.37 59.03,111.98 58.71,111.66 57.42,111.66 55.5,109.73 55.5,107.85 59.28,104.06 59.28,94.34 58.39,93.45 58.39,89.51 57.83,88.94 57.79,88.9
  BOTTOM w0.112: P9.11 61.27,119.96 v1(61.4,120.08)
H_CSI2_DY2: length 44
  TOP w0.102: 57.04,90.18 56.98,90.13 56.98,89.49 U27.AD2
  TOP w0.112: 57.04,90.18 57.04,103.87 53.72,107.19 53.72,115.06 56.66,118 v1(57.02,118)
  BOTTOM w0.112: P9.15 62.77,120.61 62.43,120.96 57.59,120.96 55.91,119.28 55.91,118.34 56.25,118 v1(57.02,118)
H_DCAN1_EN: length 77
  TOP w0.102: U27.B17 47.23,74.59 47.23,73.87 47.09,73.73 47.09,73.51
  TOP w0.127: v1(52.32,61.09) 51.82,61.09 49.53,63.37 49.53,64.64 46.48,67.69 46.48,71.63 47.09,72.24 47.09,73.51
  LY4 w0.133: v1(52.32,61.09) 52.7,60.71 68.96,60.71 69.85,59.82 72.52,59.82 77.72,54.61 89.79,54.61 93.22,58.04 105.41,58.04 v1(106.68,56.77)
  BOTTOM w0.127: R438.1 v1(106.68,56.77)
H_DCAN1_NFAULT: length 80.3
  TOP w0.102: U27.B16 47.93,74.54 47.93,73.99 48.15,73.77 48.15,73.51
  TOP w0.127: v1(53.21,62.06) 51.27,64.01 51.08,64.01 46.99,68.09 46.99,71.25 48.15,72.4 48.15,73.51
  LY4 w0.133: v1(53.21,62.06) 53.43,61.85 57.02,61.85 57.91,62.74 68.96,62.74 69.72,61.98 71.5,61.98 71.75,62.23 73.15,62.23 75.31,60.07 75.31,58.55 78.11,55.75 89.03,55.75 94.11,60.83 100.97,60.83 104.52,64.39 107.19,64.39 v1(107.95,65.15)
  BOTTOM w0.127: R439.1 v1(107.95,65.15)
H_DCAN1_RX: length 106
  TOP w0.102: 40.97,78.49 42.72,78.49 U27.H23
  TOP w0.127: v1(30.42,63.06) 30.42,71.18 35.94,76.71 38.48,76.71 40.26,78.49 40.97,78.49
  LY4 w0.133: v1(30.42,63.06) 31.62,61.85 52.58,61.85 52.96,61.47 57.28,61.47 58.17,62.36 68.71,62.36 69.47,61.59 71.5,61.59 72.52,60.58 74.04,60.58 74.93,59.69 74.93,58.42 77.98,55.37 89.28,55.37 94.23,60.33 100.58,60.33 102.11,58.8 103.38,58.8 v1(104.14,59.56)
  BOTTOM w0.127: R371.1 v1(104.14,59.56)
H_DCAN1_STB: length 74.1
  TOP w0.102: 46.28,73.51 U27.A18
  TOP w0.127: 46.28,73.51 46.28,72.57 45.09,71.37 45.09,69.72 45.72,69.09 45.72,66.93 48.26,64.39 48.26,62.23 51.56,58.93 51.56,57.91 v1(52.01,57.47)
  LY3 w0.133: v1(52.01,57.47) 52.58,58.04 56.51,58.04 57.49,57.07 61,57.07 61.21,57.28 62.36,57.28 63.12,56.52 79.79,56.52 79.83,56.47 80.73,56.47 81.58,57.32 84.95,57.32 90.62,62.99 98.17,62.99 v1(100.33,65.15)
  BOTTOM w0.127: R426.1 v1(100.33,65.15)
H_DCAN1_TX: length 108.7
  TOP w0.102: 40.97,79.12 43.35,79.12 U27.H22
  TOP w0.127: 40.97,79.12 39.24,79.12 38.23,78.11 36.58,78.11 31.88,73.41 29.46,73.41 27.18,71.12 v1(27.18,62.87)
  LY4 w0.133: v1(27.18,62.87) 28.32,62.87 28.83,62.36 30.35,62.36 30.86,61.85 31.25,61.85 31.52,61.59 52.46,61.59 52.96,61.09 57.4,61.09 57.62,61.3 61.81,61.3 62.36,61.85 68.58,61.85 69.85,60.58 71.88,60.58 72.26,60.2 73.91,60.2 74.55,59.56 74.55,58.29 77.85,54.99 89.53,54.99 94.11,59.56 v1(100.33,59.56)
  BOTTOM w0.127: R372.1 v1(100.33,59.56)
H_DDR1_A0: length 99.1
  TOP w0.102: U29.N3 v2(11.11,80.1) ; U23.N3 v2(11.11,94.33)
  TOP w0.127: R88.2 v1(10.41,69.91) ; U27.AC18 v3(46.6,88.87)
  LY3 w0.133: v2(11.11,80.1) 11.11,77.53 10.71,77.13 10.71,71.54 10.41,71.25 v1(10.41,69.91)
  LY4 w0.133: v3(46.6,88.87) 46.61,91.37 46.26,91.72 46.26,91.9 46.63,92.27 46.63,92.46 46.44,92.65 46.25,92.65 45.88,92.28 45.69,92.28 45.5,92.47 45.5,92.66 46.48,93.64 46.48,93.98 45.09,95.38 43.3,95.38 42.31,96.37 42.31,97.64 41.42,98.53 41.2,98.53 40.47,97.8 40.25,97.8 40.09,97.96 40.09,98.18 40.82,98.91 40.82,99.13 40.64,99.31 39.75,99.31 38.95,98.51 38.95,97.84 38.83,97.72 28.9,97.72 28.81,97.81 28.55,97.81 28.42,97.94 28.42,98.38 28.28,98.52 28.02,98.52 27.88,98.38 27.88,97.94 27.75,97.81 27.48,97.81 27.35,97.94 27.35,98.38 27.22,98.52 26.95,98.52 26.82,98.38 26.82,97.94 26.68,97.81 26.33,97.81 26.2,97.67 26.2,96.93 26.07,96.79 25.8,96.79 25.67,96.93 25.67,97.67 25.53,97.81 25.27,97.81 25.13,97.67 25.13,96.93 25,96.79 24.73,96.79 24.6,96.93 24.6,97.67 24.47,97.81 24.2,97.81 24.07,97.67 24.07,96.93 23.93,96.79 23.67,96.79 23.53,96.93 23.53,97.67 23.37,97.83 19.99,97.83 19.83,97.68 19.83,97.44 19.67,97.28 19.45,97.28 19.3,97.44 19.3,97.68 19.14,97.83 18.63,97.83 18.56,97.9 16.78,97.9 16.63,97.74 16.63,97.44 16.47,97.28 16.25,97.28 16.09,97.44 16.09,97.74 15.94,97.9 15.71,97.9 15.56,97.74 15.56,97.44 15.4,97.28 15.18,97.28 15.02,97.44 15.02,97.74 14.87,97.9 14.61,97.9 14.47,97.76 14.47,97.04 14.34,96.91 14.07,96.91 13.94,97.04 13.94,97.76 13.81,97.9 13.54,97.9 13.41,97.76 13.41,97.04 13.27,96.91 13.01,96.91 12.87,97.04 12.87,97.76 12.74,97.9 12.08,97.9 11.51,97.33 11.51,94.73 v2(11.11,94.33)
  BOTTOM w0.127: v2(11.11,94.33) 11.11,93.7 11.24,93.57 11.61,93.57 11.89,93.29 11.89,92.28 11.76,92.16 9.75,92.16 9.63,92.03 9.63,91.77 9.75,91.65 11.76,91.65 11.89,91.52 11.89,91.08 11.52,90.72 11.52,88.56 9.25,86.28 9.25,82.5 9.28,82.5 9.92,81.86 9.92,81.5 10.12,81.3 10.48,81.3 10.71,81.07 10.71,80.51 v2(11.11,80.1)
H_DDR1_A1: length 95.2
  TOP w0.102: U29.P7 v2(10.31,76.11)
  TOP w0.127: v1(42.01,101.23) 42.01,100.53 43.18,99.36 43.18,97.6 44.64,96.14 44.64,95.69 44.12,95.17 44.12,93.23 45.63,91.72 U27.AE19 ; v2(10.31,90.33) U23.P7
  LY3 w0.133: v1(9.78,70.36) 9.78,70.99 9.65,71.12 9.65,72.77 9.92,73.03 9.92,75.71 v2(10.31,76.11) 10.31,77.43 10.71,77.83 10.71,81.87 9.92,82.66 9.92,82.9 9.78,83.03 8.72,83.03 8.59,83.16 8.59,83.43 8.72,83.56 9.78,83.56 9.92,83.7 9.92,83.97 9.78,84.1 8.72,84.1 8.59,84.23 8.59,84.5 8.72,84.63 9.78,84.63 9.92,84.77 9.92,89.93 v2(10.31,90.33)
  LY4 w0.133: v2(10.31,90.33) 10.31,91.61 8.29,93.63 8.29,97.41 10.54,99.66 19.29,99.66 19.42,99.8 19.42,100.74 19.56,100.88 19.82,100.88 19.96,100.74 19.96,99.8 20.09,99.66 20.36,99.66 20.49,99.8 20.49,100.74 20.62,100.88 20.89,100.88 21.02,100.74 21.02,99.8 21.16,99.66 21.42,99.66 21.56,99.8 21.56,100.74 21.69,100.88 21.96,100.88 22.09,100.74 22.09,99.8 22.22,99.66 22.49,99.66 22.62,99.8 22.62,100.74 22.76,100.88 23.02,100.88 23.16,100.74 23.16,99.8 23.29,99.66 23.56,99.66 23.69,99.8 23.69,100.74 23.82,100.88 24.09,100.88 24.22,100.74 24.22,99.8 24.36,99.66 24.66,99.66 25.81,100.81 41.59,100.81 v1(42.01,101.23)
  BOTTOM w0.127: v1(9.78,70.36) R284.2
H_DDR1_A2: length 108.6
  TOP w0.102: 45.95,90.58 45.95,89.51 U27.AD19 ; U23.P3 v2(10.31,94.33) ; U29.P3 v2(10.31,80.1)
  TOP w0.127: 45.95,90.58 45.95,91.76 44.42,93.28 44.42,95.11 44.89,95.58 44.89,96.25 43.46,97.68 43.46,99.49 42.9,100.05 v1(42.9,100.99) ; R85.2 v1(6.99,69.91)
  LY3 w0.133: v1(6.99,69.91) 6.99,75.03 10.31,78.36 v2(10.31,80.1)
  BOTTOM w0.127: v2(10.31,80.1) 9.92,80.5 9.34,80.5 9.11,80.73 9.11,81.07 9.11,82 8.76,82.35 8.76,86.46 10.72,88.42 10.72,90.17 10.71,90.18 10.71,90.97 10.44,91.24 9.55,91.24 9.19,91.59 9.19,92.53 9.32,92.66 11.2,92.66 11.33,92.79 11.33,93.04 11.2,93.17 9.32,93.17 9.19,93.29 9.19,93.55 9.42,93.78 10.16,93.78 10.31,93.93 v2(10.31,94.33) 9.92,94.72 9.92,101.44 10.33,101.85 10.72,101.85 10.85,101.73 10.85,100.1 10.97,99.97 11.2,99.97 11.36,100.13 11.36,101.73 11.48,101.85 11.74,101.85 11.86,101.73 11.86,100.18 12.03,100.02 12.21,100.02 12.37,100.18 12.37,101.73 12.5,101.85 12.88,101.85 13,101.73 13,100.94 13.13,100.81 13.39,100.81 13.51,100.94 13.51,101.73 13.64,101.85 13.89,101.85 14.02,101.73 14.02,100.94 14.15,100.81 14.4,100.81 14.53,100.94 14.53,101.73 14.66,101.85 14.91,101.85 15.04,101.73 15.04,100.94 15.16,100.81 15.42,100.81 15.54,100.94 15.54,101.73 15.67,101.85 15.93,101.85 16.05,101.73 16.05,100.94 16.18,100.81 16.43,100.81 16.56,100.94 16.56,101.73 16.69,101.85 16.94,101.85 17.07,101.73 17.07,100.94 17.2,100.81 17.45,100.81 17.58,100.94 17.58,101.73 17.7,101.85 17.96,101.85 18.08,101.73 18.08,100.94 18.21,100.81 18.47,100.81 18.59,100.94 18.59,101.73 18.72,101.85 18.97,101.85 19.1,101.73 19.1,100.94 19.23,100.81 39.81,100.81 40.65,101.65 42.24,101.65 v1(42.9,100.99)
H_DDR1_A3: length 102.3
  TOP w0.102: U23.N2 v2(11.11,95.13) ; U29.N2 v2(11.11,80.9)
  TOP w0.127: U27.AB19 45.38,88.14 v3(43.94,88.14) ; R90.2 v1(12.7,69.91)
  LY3 w0.133: v1(12.7,69.91) 12.7,72.77 11.51,73.96 11.51,80.5 11.11,80.9 v2(11.11,80.9) 11.51,81.3 11.51,85.14 10.72,85.93 10.72,90.73 11.48,91.49 13.84,91.49 14.15,91.8 14.15,92.61 13.69,93.07 12.4,93.07 11.52,93.94 11.52,94.73 v2(11.11,95.13) 11.51,95.53 11.51,98.73 11.7,98.93 11.7,99.93 12.19,100.42 28.59,100.42 29.35,101.18 34.11,101.18 34.25,101.05 34.25,100.55 34.38,100.42 34.65,100.42 34.78,100.55 34.78,101.05 34.91,101.18 35.18,101.18 35.31,101.05 35.31,100.55 35.45,100.42 35.71,100.42 35.85,100.55 35.85,101.05 35.98,101.18 36.25,101.18 36.38,101.05 36.38,100.55 36.52,100.42 36.78,100.42 36.92,100.55 36.92,101.05 37.05,101.18 37.32,101.18 37.45,101.05 37.45,100.55 37.58,100.42 37.85,100.42 37.98,100.55 37.98,101.05 38.12,101.18 38.38,101.18 38.52,101.05 38.52,100.55 38.65,100.42 39.17,100.42 41.15,98.45 43.38,98.45 43.76,98.07 47.02,98.07 48.01,97.08 48.01,93.82 47.41,93.22 46.07,93.22 45.51,92.66 45.51,89.92 45.38,89.79 45.09,89.79 44.96,89.93 44.96,92.7 44.82,92.84 44.56,92.84 44.42,92.7 44.42,89.69 45.09,89.03 45.09,88.77 44.45,88.14 v3(43.94,88.14)
H_DDR1_A4: length 94.7
  TOP w0.102: 44.66,90.58 44.66,89.52 U27.AD20 ; U29.P8 v2(10.31,75.31)
  TOP w0.127: 44.66,90.58 44.66,91.62 43.36,92.91 43.36,96.71 42.27,97.8 42.27,99.8 41.45,100.61 41.45,100.9 v1(41.13,101.23) ; v2(10.31,89.53) U23.P8
  LY4 w0.133: v1(41.13,101.23) 19.16,101.23 18.27,100.34 17.77,100.34 17.64,100.47 17.64,101.18 17.51,101.31 17.24,101.31 17.11,101.18 17.11,100.47 16.97,100.34 16.71,100.34 16.57,100.47 16.57,101.18 16.44,101.31 16.17,101.31 16.04,101.18 16.04,100.47 15.91,100.34 15.64,100.34 15.51,100.47 15.51,101.18 15.37,101.31 15.11,101.31 14.97,101.18 14.97,100.47 14.84,100.34 14.57,100.34 14.44,100.47 14.44,101.18 14.31,101.31 14.04,101.31 13.91,101.18 13.91,100.47 13.77,100.34 13.51,100.34 13.37,100.47 13.37,101.18 13.24,101.31 12.97,101.31 12.84,101.18 12.84,100.47 12.71,100.34 12.44,100.34 12.31,100.47 12.31,101.18 12.17,101.31 11.91,101.31 11.77,101.18 11.77,100.47 11.64,100.34 10.75,100.34 8,97.58 8,93.26 9.91,91.34 9.91,89.93 v2(10.31,89.53) 9.91,89.13 9.91,88.56 9.68,88.33 8.88,88.33 8.37,88.33 7.9,87.86 7.9,87.6 7.77,87.46 7.42,87.46 7.29,87.33 7.29,87.06 7.42,86.93 7.77,86.93 7.9,86.8 7.9,85.76 7.77,85.63 7.47,85.63 7.34,85.5 7.34,85.23 7.47,85.1 7.77,85.1 7.9,84.96 7.9,76.71 8.11,76.5 9.68,76.5 9.91,76.27 9.91,75.71 v2(10.31,75.31) 9.91,74.91 9.91,72.89 10.92,71.88 v1(10.92,70.36)
  BOTTOM w0.127: v1(10.92,70.36) R283.2
H_DDR1_A5: length 104.3
  TOP w0.102: U29.P2 v2(10.31,80.9) ; U23.P2 v2(10.31,95.13)
  TOP w0.127: U27.AE20 44.98,91.65 43.61,93.02 43.61,96.81 42.75,97.68 v1(42.75,98.88)
  LY3 w0.133: v1(6.35,70.36) 6.35,74.9 9.91,78.47 9.91,80.51 v2(10.31,80.9) 9.91,81.3 9.91,81.87 9.58,82.19 8.64,82.19 8.2,82.63 8.2,91.55 8.34,91.68 9.09,91.68 9.22,91.81 9.22,92.08 9.09,92.21 8.34,92.21 8.2,92.35 8.2,92.58 8.53,92.91 10.21,92.91 10.71,93.41 10.71,94.23 10.72,94.23 10.72,94.73 v2(10.31,95.13) 10.72,95.53 10.72,96.23 10.26,96.68 10.26,98.35 10.6,98.69 10.89,98.69 11.31,99.11 11.31,99.69 11.12,99.89 11.12,100.5 11.48,100.86 14.43,100.86 14.56,100.99 14.56,101.65 14.7,101.78 14.96,101.78 15.1,101.65 15.1,100.99 15.23,100.86 15.5,100.86 15.63,100.99 15.63,101.65 15.76,101.78 16.03,101.78 16.16,101.65 16.16,100.99 16.3,100.86 16.56,100.86 16.7,100.99 16.7,101.65 16.83,101.78 17.1,101.78 17.23,101.65 17.23,100.99 17.36,100.86 17.63,100.86 17.76,100.99 17.76,101.65 17.9,101.78 18.16,101.78 18.3,101.65 18.3,100.99 18.43,100.86 18.7,100.86 18.83,100.99 18.83,101.65 18.96,101.78 19.23,101.78 19.36,101.65 19.36,100.99 19.5,100.86 19.76,100.86 19.9,100.99 19.9,101.65 20.03,101.78 20.3,101.78 20.43,101.65 20.43,100.99 20.56,100.86 20.83,100.86 20.96,100.99 20.96,101.65 21.1,101.78 21.36,101.78 21.5,101.65 21.5,100.99 21.63,100.86 21.9,100.86 22.03,100.99 22.03,101.65 22.16,101.78 22.43,101.78 22.56,101.65 22.56,100.99 22.7,100.86 22.96,100.86 23.1,100.99 23.1,101.65 23.23,101.78 23.5,101.78 23.63,101.65 23.63,100.99 23.76,100.86 24.03,100.86 24.16,100.99 24.16,101.65 24.3,101.78 24.56,101.78 24.7,101.65 24.7,100.99 24.83,100.86 25.1,100.86 25.23,100.99 25.23,101.65 25.36,101.78 25.63,101.78 25.76,101.65 25.76,100.99 25.9,100.86 26.16,100.86 26.3,100.99 26.3,101.65 26.43,101.78 26.7,101.78 26.83,101.65 26.83,100.99 26.96,100.86 27.23,100.86 27.36,100.99 27.36,101.65 27.5,101.78 27.76,101.78 27.9,101.65 27.9,100.99 28.03,100.86 28.3,100.86 28.43,100.99 28.43,101.65 28.56,101.78 38.41,101.78 41.31,98.88 v1(42.75,98.88)
  BOTTOM w0.127: v1(6.35,70.36) R287.2
H_DDR1_A6: length 92.7
  TOP w0.102: U23.R8 v2(9.51,89.53) ; U29.R8 v2(9.51,75.31)
  TOP w0.127: v3(46.6,86.92) U27.AA18 ; R87.2 v1(9.27,69.91)
  LY4 w0.133: v1(9.27,69.91) 9.27,71.37 9.11,71.53 9.11,74.91 v2(9.51,75.31) 9.11,75.71 8.88,75.71 8.19,75.71 6.6,77.29 6.6,77.55 6.74,77.69 7.31,77.69 7.44,77.82 7.44,78.09 7.31,78.22 6.74,78.22 6.6,78.35 6.6,88.24 7.49,89.13 9.11,89.13 v2(9.51,89.53) 9.12,89.93 9.12,91.47 7.7,92.89 7.7,97.74 11.61,101.65 43.82,101.65 48.77,96.71 48.77,89.79 48.93,89.63 48.93,88.04 47.8,86.92 v3(46.6,86.92)
H_DDR1_A7: length 103.2
  TOP w0.102: U29.R2 v2(9.51,80.9) ; U23.R2 v2(9.51,95.13)
  TOP w0.127: U27.AA20 v3(44.65,87.57)
  LY3 w0.133: v1(5.21,70.36) 5.21,75.46 9.12,79.37 9.12,80.51 v2(9.51,80.9) 9.27,80.9 8.88,81.3 8,81.3 7.72,81.58 7.72,81.82 7.59,81.95 7.19,81.95 7.06,82.09 7.06,82.35 7.19,82.49 7.59,82.49 7.72,82.62 7.72,82.89 7.59,83.02 7.19,83.02 7.06,83.15 7.06,83.42 7.19,83.55 7.59,83.55 7.72,83.69 7.72,93.07 8.05,93.4 9.42,93.4 9.91,93.88 9.91,94.73 v2(9.51,95.13) 9.92,95.53 9.92,101.27 10.71,102.07 11.06,102.07 11.2,101.93 11.2,101.38 11.33,101.25 11.6,101.25 11.73,101.38 11.73,101.93 11.86,102.07 12.13,102.07 12.26,101.93 12.26,101.38 12.4,101.25 12.66,101.25 12.8,101.38 12.8,101.93 12.93,102.07 13.2,102.07 13.33,101.93 13.33,101.38 13.47,101.25 13.73,101.25 13.87,101.38 13.87,101.93 14,102.07 38.55,102.07 41.42,99.19 42.12,99.19 42.25,99.32 43.12,99.32 44.05,98.39 47.17,98.39 48.36,97.2 48.36,93.55 47.2,92.39 47.2,89.8 47.08,89.68 46.8,89.68 46.66,89.81 46.66,92.45 46.53,92.58 46.18,92.58 46.05,92.45 46.05,89.87 45.47,89.28 45.47,88.65 44.65,87.83 v3(44.65,87.57)
  BOTTOM w0.127: v1(5.21,70.36) R288.2
H_DDR1_A8: length 99.3
  TOP w0.102: U29.T8 v2(8.71,75.31) ; U23.T8 v2(8.71,89.53)
  TOP w0.127: R86.2 v1(8.13,69.91) ; U27.Y21 v3(44,86.92)
  LY4 w0.133: v3(44,86.92) 44,87.57 45.21,88.77 45.21,90.93 44.45,91.69 44.45,93.22 v1(44.96,93.73) ; v2(8.71,89.53) 7.11,89.53 6.1,88.52 6.1,76.96 6.23,76.82 6.47,76.82 6.6,76.69 6.6,76.42 6.47,76.29 6.23,76.29 6.1,76.16 6.1,75.44 6.23,75.31 v2(8.71,75.31) 7.98,74.57 7.98,71.02 8.13,70.87 v1(8.13,69.91)
  BOTTOM w0.127: v1(44.96,93.73) 46.1,94.87 46.1,100.71 44.4,102.41 32.18,102.41 32,102.23 30.66,102.23 30.48,102.41 29.26,102.41 29.13,102.28 29.13,101.81 29.01,101.69 28.75,101.69 28.62,101.81 28.62,102.28 28.5,102.41 28.24,102.41 28.12,102.28 28.12,101.81 27.99,101.69 27.74,101.69 27.61,101.81 27.61,102.28 27.48,102.41 27.23,102.41 27.1,102.28 27.1,101.81 26.97,101.69 26.72,101.69 26.59,101.81 26.59,102.28 26.47,102.41 26.21,102.41 26.08,102.28 26.08,101.81 25.96,101.69 25.7,101.69 25.58,101.81 25.58,102.28 25.45,102.41 8.8,102.41 8.31,101.91 8.31,91.36 9.11,90.56 9.11,90.17 8.71,89.77 v2(8.71,89.53)
H_DDR1_A9: length 108.6
  TOP w0.102: U29.R3 v2(9.51,80.1) ; U23.R3 v2(9.51,94.33)
  TOP w0.127: U27.AC20 v3(44.65,88.87) ; R84.2 v1(5.84,69.91)
  LY3 w0.133: v2(9.51,80.1) 9.51,78.46 5.84,74.79 v1(5.84,69.91)
  BOTTOM w0.127: v3(44.65,88.87) 44.11,89.41 42.24,89.41 42.11,89.54 42.11,92.91 42.26,93.06 42.58,93.06 42.81,92.83 42.81,90.02 42.91,89.92 43.28,89.92 43.41,90.05 43.41,94.01 44.58,95.18 44.58,97.54 45.72,98.68 45.72,100.46 44.2,101.98 40.13,101.98 39.39,101.24 23,101.24 22.88,101.36 22.88,102.01 22.75,102.13 22.5,102.13 22.37,102.01 22.37,101.36 22.24,101.24 21.99,101.24 21.86,101.36 21.86,102.01 21.73,102.13 21.48,102.13 21.35,102.01 21.35,101.36 21.23,101.24 20.97,101.24 20.85,101.36 20.85,102.01 20.72,102.13 20.46,102.13 20.34,102.01 20.34,101.36 20.21,101.24 19.96,101.24 19.83,101.36 19.83,102.01 19.7,102.13 9.43,102.13 9.12,101.83 9.12,94.72 v2(9.51,94.33) 8.74,93.55 8.74,91.47 9.3,90.91 9.49,90.91 9.91,90.49 9.91,88.44 8.32,86.86 8.32,81.54 8.32,78.22 8.64,77.9 9.29,77.9 9.51,78.12 9.51,78.66 9.39,78.79 9.04,78.79 8.92,78.91 8.92,79.17 9.04,79.3 9.39,79.3 9.51,79.42 v2(9.51,80.1)
H_DDR1_A10: length 96.9
  TOP w0.102: U23.L7 v2(12.71,90.33) ; U29.L7 v2(12.71,76.11)
  TOP w0.127: U27.AA21 43.94,87.63 v3(43.56,87.63) ; U23.L7 13.11,92.07 13.24,92.2 22.63,92.2 23.09,92.67 23.09,93.92 23.69,94.51 23.69,96.48 23.82,96.61 24.07,96.61 24.18,96.49 24.18,95.59 24.19,95.59 24.19,94.65 24.32,94.52 24.5,94.52 24.63,94.65 24.63,96.64 24.76,96.77 25.01,96.77 25.14,96.64 25.14,96.09 25.26,95.96 25.52,95.96 25.64,96.09 25.64,96.64 25.77,96.77 26.03,96.77 26.15,96.64 26.15,96.09 26.28,95.96 26.53,95.96 26.66,96.09 26.66,96.64 26.79,96.77 27.04,96.77 27.17,96.64 27.17,96.09 27.3,95.96 27.55,95.96 27.68,96.09 27.68,96.64 27.8,96.77 28.06,96.77 28.18,96.64 28.18,96.09 28.31,95.96 28.57,95.96 28.69,96.09 28.69,96.64 28.82,96.77 29.07,96.77 29.2,96.64 29.2,96.09 29.33,95.96 29.58,95.96 29.71,96.09 29.71,96.64 29.84,96.77 30.09,96.77 30.22,96.64 30.22,96.09 30.34,95.96 30.6,95.96 30.72,96.09 30.72,96.64 30.85,96.77 31.11,96.77 31.23,96.64 31.23,96.09 31.36,95.96 31.61,95.96 31.74,96.09 31.74,96.64 31.87,96.77 32.12,96.77 32.25,96.64 32.25,96.09 32.38,95.96 32.63,95.96 32.76,96.09 32.76,96.64 32.88,96.77 33.14,96.77 33.26,96.64 33.26,96.09 33.39,95.96 33.65,95.96 33.77,96.09 33.77,96.64 33.9,96.77 34.15,96.77 34.28,96.64 34.28,96.09 34.41,95.96 34.66,95.96 34.79,96.09 34.79,96.64 34.92,96.77 35.17,96.77 35.3,96.64 35.3,96.09 35.42,95.96 35.68,95.96 35.8,96.09 35.8,96.64 35.93,96.77 36.19,96.77 36.31,96.64 36.31,96.09 36.44,95.96 36.69,95.96 36.82,96.09 36.82,96.64 36.95,96.77 37.2,96.77 37.33,96.64 37.33,96.09 37.46,95.96 37.71,95.96 37.84,96.09 37.84,96.64 37.96,96.77 38.22,96.77 38.34,96.64 38.34,96.09 38.47,95.96 38.73,95.96 38.85,96.09 38.85,96.64 38.98,96.77 39.23,96.77 39.36,96.64 39.36,96.09 39.49,95.96 39.74,95.96 39.87,95.83 39.87,94.38 40,94.26 40.25,94.26 40.38,94.38 40.38,95.83 40.5,95.96 40.82,95.96 40.94,95.83 40.94,95.55 41.07,95.43 41.33,95.43 41.45,95.55 41.45,95.83 41.58,95.96 42.6,95.96 42.82,95.73 v1(42.82,94.06) ; R92.2 v1(14.99,69.91)
  LY4 w0.133: v1(42.82,94.06) 41.91,93.14 41.91,87.76 42.47,87.2 43.13,87.2 v3(43.56,87.63) ; v1(14.99,69.91) 14.99,70.48 14.73,70.74 14.73,71.63 13.11,73.25 13.11,75.7 v2(12.71,76.11) 13.11,76.5 13.11,88.87 v2(12.71,90.33)
H_DDR1_A11: length 100.9
  TOP w0.102: U29.R7 v2(9.51,76.11) ; U23.R7 v2(9.51,90.33)
  TOP w0.127: U23.R7 9.91,91.98 10.9,92.96 21.06,92.96 22.63,94.53 22.63,99.32 23.2,99.89 23.75,99.89 23.88,100.02 23.88,100.69 24.01,100.82 24.26,100.82 24.39,100.69 24.39,100.02 24.52,99.89 24.77,99.89 24.9,100.02 24.9,100.69 25.02,100.82 25.28,100.82 25.41,100.69 25.41,100.02 25.53,99.89 25.79,99.89 25.91,100.02 25.91,100.69 26.04,100.82 26.29,100.82 26.42,100.69 26.42,100.02 26.55,99.89 26.8,99.89 26.93,100.02 26.93,100.69 27.06,100.82 27.31,100.82 27.44,100.69 27.44,100.02 27.56,99.89 27.82,99.89 27.95,100.02 27.95,100.69 28.07,100.82 28.33,100.82 28.45,100.69 28.45,100.02 28.58,99.89 28.83,99.89 28.96,100.02 28.96,100.69 29.09,100.82 29.34,100.82 29.47,100.69 29.47,100.02 29.6,99.89 29.85,99.89 29.98,100.02 29.98,100.69 30.1,100.82 30.36,100.82 30.49,100.69 30.49,100.02 30.61,99.89 30.87,99.89 30.99,100.02 30.99,100.69 31.12,100.82 31.37,100.82 31.5,100.69 31.5,100.02 31.63,99.89 31.88,99.89 32.01,100.02 32.01,100.69 32.14,100.82 32.39,100.82 32.52,100.69 32.52,100.02 32.64,99.89 32.9,99.89 33.03,100.02 33.03,100.69 33.15,100.82 33.41,100.82 33.53,100.69 33.53,100.02 33.66,99.89 33.91,99.89 34.04,100.02 34.04,100.69 34.17,100.82 34.42,100.82 34.55,100.69 34.55,100.02 34.68,99.89 34.93,99.89 35.06,100.02 35.06,100.69 35.18,100.82 35.44,100.82 35.57,100.69 35.57,100.02 35.69,99.89 35.95,99.89 36.07,100.02 36.07,100.69 36.2,100.82 36.45,100.82 36.58,100.69 36.58,100.02 36.71,99.89 36.96,99.89 37.09,100.02 37.09,100.69 37.22,100.82 37.47,100.82 37.6,100.69 37.6,100.02 37.72,99.89 37.98,99.89 38.11,100.02 38.11,100.69 38.23,100.82 38.49,100.82 38.61,100.69 38.61,100.02 38.74,99.89 38.99,99.89 39.12,100.02 39.12,100.69 39.25,100.82 39.5,100.82 39.63,100.69 39.63,100.02 39.76,99.89 40.44,99.89 41.15,99.19 41.15,97.69 v1(40.64,97.18) ; U27.AC21 v3(44,88.87)
  LY3 w0.133: v1(8.64,70.36) 8.64,70.87 9.11,71.34 9.11,75.7 v2(9.51,76.11) ; v3(44,88.87) 44,94.25 41.81,96.44 41.81,97.1 41.55,97.36 40.82,97.36 v1(40.64,97.18)
  BOTTOM w0.127: v2(9.51,90.33) 9.51,90.09 9.12,89.69 9.12,89.65 9.11,89.64 9.11,88.51 7.92,87.33 7.92,78.03 8.23,77.72 8.23,77.39 v2(9.51,76.11) ; v1(8.64,70.36) R285.2
